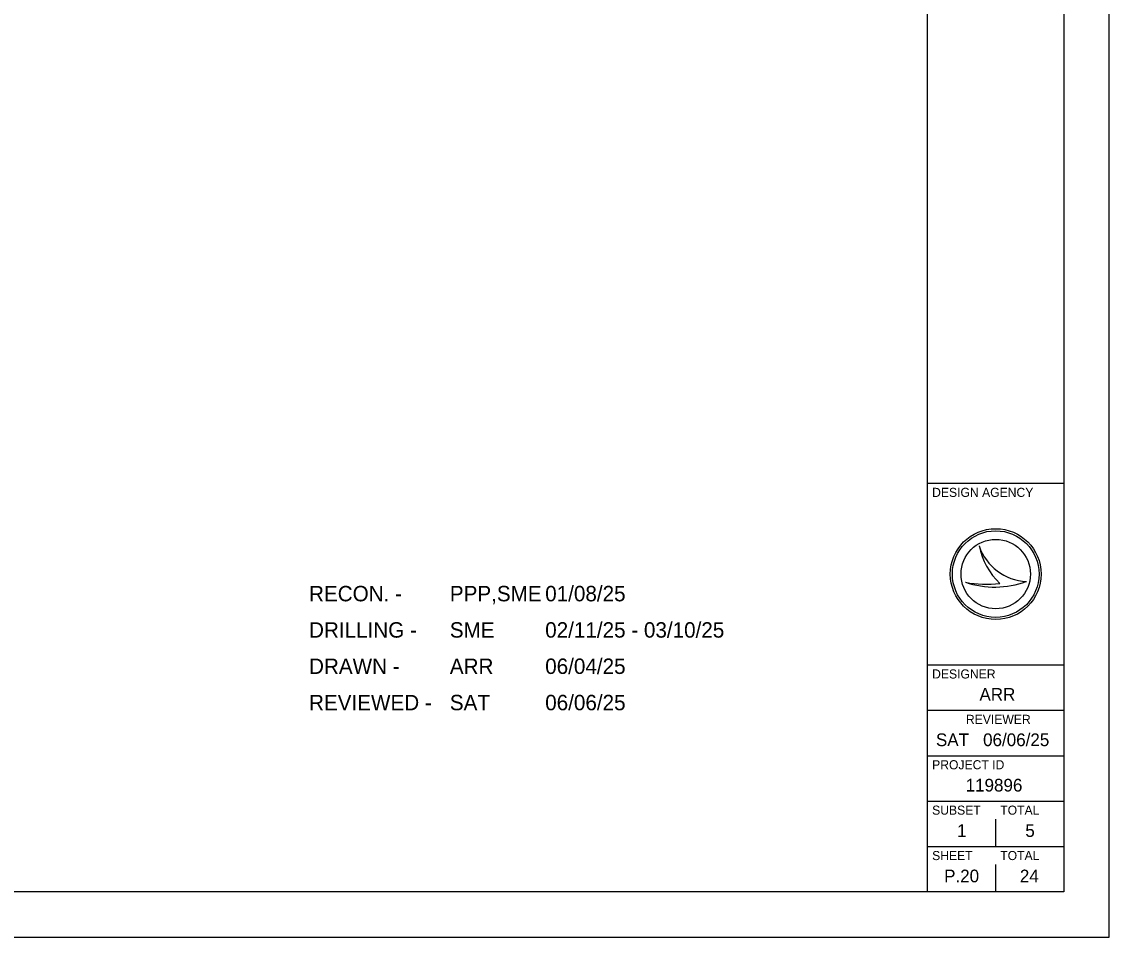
# Model space of a CAD drawing. Extents: x 0 to 34, y 0 to 22.
# Drawn here: x 22.03 to 34, y 0 to 10.08 of the extents above; entities that cross this region are included whole.
import ezdxf

# ---------------------------------------------------------------- set-up
doc = ezdxf.new("R2010")
doc.units = 0
for name, color, linetype in [('SH_Border', 7, 'Continuous'), ('SH_Cut_Line', 7, 'Continuous'), ('SH_Data', 7, 'Continuous'), ('SH_Text', 7, 'Continuous')]:
    doc.layers.add(name, color=color, linetype=linetype)

msp = doc.modelspace()

# ---------------------------------------------------------------- linework, layer by layer
at = {"layer": 'SH_Border'}
for p, q in [((32, 0.5), (32, 21.5)), ((32, 5), (33.5, 5)), ((32, 3), (33.5, 3)), ((32, 2.5), (33.5, 2.5)), ((32, 2), (33.5, 2)), ((32, 1.5), (33.5, 1.5)), ((32, 1), (33.5, 1))]:
    msp.add_line(p, q, dxfattribs=at)
msp.add_lwpolyline([(1.5, 21.5), (33.5, 21.5), (33.5, 0.5), (1.5, 0.5)], close=True, dxfattribs=at)
at = {"layer": 'SH_Cut_Line'}
msp.add_lwpolyline([(0, 0), (34, 0), (34, 22), (0, 22)], close=True, dxfattribs=at)
at = {"layer": 'SH_Data'}
for p, q in [((32.567, 4.31), (32.567, 4.31)), ((32.75, 4), (32.75, 4)), ((32.417, 3.91), (32.417, 3.91)), ((33.087, 3.919), (33.087, 3.919)), ((32.75, 1), (32.75, 1.3)), ((32.75, 0.5), (32.75, 0.8)), ((32.375, 0.675), (32.375, 0.675))]:
    msp.add_line(p, q, dxfattribs=at)
for radius in [0.5, 0.477, 0.477, 0.382]:
    msp.add_circle((32.75, 4), radius, dxfattribs=at)
for centre, radius, start, end in [((33.116, 4.498), 0.58, 198.9257, 198.9319), ((33.347, 4.47), 0.796, 191.6379, 191.6421), ((33.116, 4.498), 0.58, 198.9319, 267.1657), ((33.347, 4.47), 0.796, 191.6421, 226.0947), ((32.739, 4.87), 1.013, 251.4576, 290.0832), ((32.648, 5.154), 1.266, 259.4964, 259.4995), ((32.739, 4.87), 1.013, 251.4527, 251.4576), ((32.648, 5.154), 1.266, 259.4995, 276.6672)]:
    msp.add_arc(centre, radius, start, end, dxfattribs=at)

# ---------------------------------------------------------------- texts
for s, height, p in [('DESIGN AGENCY', 0.1, (32.05, 4.85)), ('DESIGNER', 0.1, (32.05, 2.85)), ('ARR', 0.14, (32.571, 2.605)), ('REVIEWER', 0.1, (32.422, 2.35)), ('SAT', 0.14, (32.092, 2.105)), ('06/06/25', 0.14, (32.611, 2.105)), ('PROJECT ID', 0.1, (32.05, 1.85)), ('SUBSET', 0.1, (32.05, 1.35)), ('TOTAL', 0.1, (32.8, 1.35)), ('1', 0.14, (32.325, 1.105)), ('5', 0.14, (33.076, 1.105)), ('SHEET', 0.1, (32.05, 0.85)), ('TOTAL', 0.1, (32.8, 0.85)), ('P.20', 0.14, (32.182, 0.605)), ('24', 0.14, (33.016, 0.605))]:
    msp.add_text(s, height=height, dxfattribs=at).set_placement(p)
at = {"layer": 'SH_Text'}
for s, height, p in [('RECON. -', 0.17, (25.19, 3.7)), ('PPP,SME', 0.17, (26.74, 3.7)), ('01/08/25', 0.17, (27.79, 3.7)), ('DRILLING -', 0.17, (25.19, 3.3)), ('SME', 0.17, (26.74, 3.3)), ('02/11/25 - 03/10/25', 0.17, (27.79, 3.3)), ('DRAWN -', 0.17, (25.19, 2.9)), ('ARR', 0.17, (26.74, 2.9)), ('06/04/25', 0.17, (27.79, 2.9)), ('REVIEWED -', 0.17, (25.19, 2.5)), ('SAT', 0.17, (26.74, 2.5)), ('06/06/25', 0.17, (27.79, 2.5)), ('119896', 0.14, (32.419, 1.605))]:
    msp.add_text(s, height=height, dxfattribs=at).set_placement(p)

doc.saveas('drawing.dxf')
